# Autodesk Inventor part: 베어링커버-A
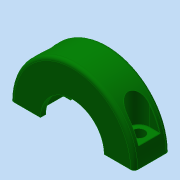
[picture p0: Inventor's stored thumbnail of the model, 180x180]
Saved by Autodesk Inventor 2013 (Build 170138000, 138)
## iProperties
Created: 2018-01
Part Number: 베어링커버-A
Material: 알루미늄 6061
Document SubType Name: Modeling
Designer: mduedu
Density: 2.71 g/cm^3
Mass: 7.21303 g
Surface Area: 19.9383 cm^2
Volume: 2.66163 cm^3
Author: mduedu
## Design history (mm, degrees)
sketch "스케치1"
  geometry: L1 (-17.5, 0)-(17.5, 0); A1 r 17.5 centre (0, 0) between (-17.5, 0) and (17.5, 0); 2 further points
  constraints: 2 coincident, 2 end point, 2 point on circle, 1 centre point, 1 horizontal, 1 midpoint
  dimensions: "d0" = 35 diameter of A1
extrude "돌출1" new body sketch "스케치1" stored distance "d1" = 10; taper "d2" = 0 deg
sketch "스케치2"
  geometry: C1 r 11 at (0, 0); C2 r 9 at (0, 0); 1 further point
  constraints: 2 centre point, 2 coincident
  dimensions: "d3" = 22 diameter of C1; "d4" = 18 diameter of C2
extrude "돌출2" cut sketch "스케치2" stored distance "d5" = 7; taper "d6" = 0 deg
extrude "돌출3" cut sketch "스케치2" stored distance "d7" = 7; taper "d8" = 0 deg
fillet "모깎기1" dims "d9" = 0.3
fillet "모깎기2" dims "d10" = 1
node "작업 평면1"
sketch "스케치3"
  geometry: L1 (-15.5, -3.5)-(33.5, -3.5) reference; L2 (-4.771, -6.5)-(-7.771, -6.5); L3 (-7.771, -6.5)-(-7.771, -0.5); L4 (-7.771, -0.5)-(-4.771, -0.5); L5 (-0.46, -7)-(1.517, -7) reference; L6 (1.517, -7)-(1.517, -8.5) reference; L7 (1.517, -8.5)-(-6.724, -8.5) reference; L8 (-7.771, -7.5)-(-7.771, 0.5) reference; L9 (-6.724, 1.5)-(1.517, 1.5) reference; L10 (1.517, 1.5)-(1.517, 0) reference; L11 (1.517, 0)-(-0.46, 0) reference; L12 (-0.798, -0.3)-(-0.798, -6.7) reference; L13 (18.798, -6.7)-(18.798, -0.3) reference; L14 (18.46, 0)-(16.483, 0) reference; L15 (16.483, 0)-(16.483, 1.5) reference; L16 (16.483, 1.5)-(24.724, 1.5) reference; L17 (25.771, 0.5)-(25.771, -7.5) reference; L18 (24.724, -8.5)-(16.483, -8.5) reference; L19 (16.483, -8.5)-(16.483, -7) reference; L20 (16.483, -7)-(18.46, -7) reference; A1 r 3 centre (-4.771, -3.5) between (-4.771, -6.5) and (-4.771, -0.5); 1 further point
  constraints: 6 end point, 2 point on circle, 2 tangent, 1 centre point, 1 collinear, 1 horizontal, 1 parallel, 1 perpendicular, 1 point on line, 8 other
  dimensions: "d12" = 6 distance between parallel lines of L4 L2; "d14" = 6 dimension on A1 L3
extrude "돌출4" cut sketch "스케치3" stored distance "d15" = 0; taper "d16" = 0 deg
sketch "스케치4"
  geometry: 7 further points
  constraints: 4 vertical alignment, 2 horizontal alignment
sketch "스케치5"
  geometry: 2 further points
  constraints: 2 other
hole "구멍1" sketch "스케치5" at (-22.771, 3.5), (4.771, 3.5) diameter "d17" = 3.4; stored, may be unused: countersink angle "d21" = 90 deg, drill point angle "d23" = 0 deg; dims "d18" = 6, "d19" = 4, "d20" = 2, "d22" = 8
fillet "모깎기3" dims "d24" = 0.1
node "솔리드1"
mirror "대칭1"
node "절단 모서리 투영1"
other parameters: "d11" = -5
